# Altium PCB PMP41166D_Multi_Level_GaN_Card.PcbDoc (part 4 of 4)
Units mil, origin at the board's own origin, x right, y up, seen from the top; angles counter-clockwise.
Board outline 3221.72 x 1840 mil, 6 copper layers (Top Layer, Signal Layer 1, Signal Layer 2, Signal Layer 3, Signal Layer 4, Bottom Layer), stack 51.8 mil thick; 155 components, 123 nets, 580 pads, 278 vias.
Unrouted connection lines stored in the file: 2.
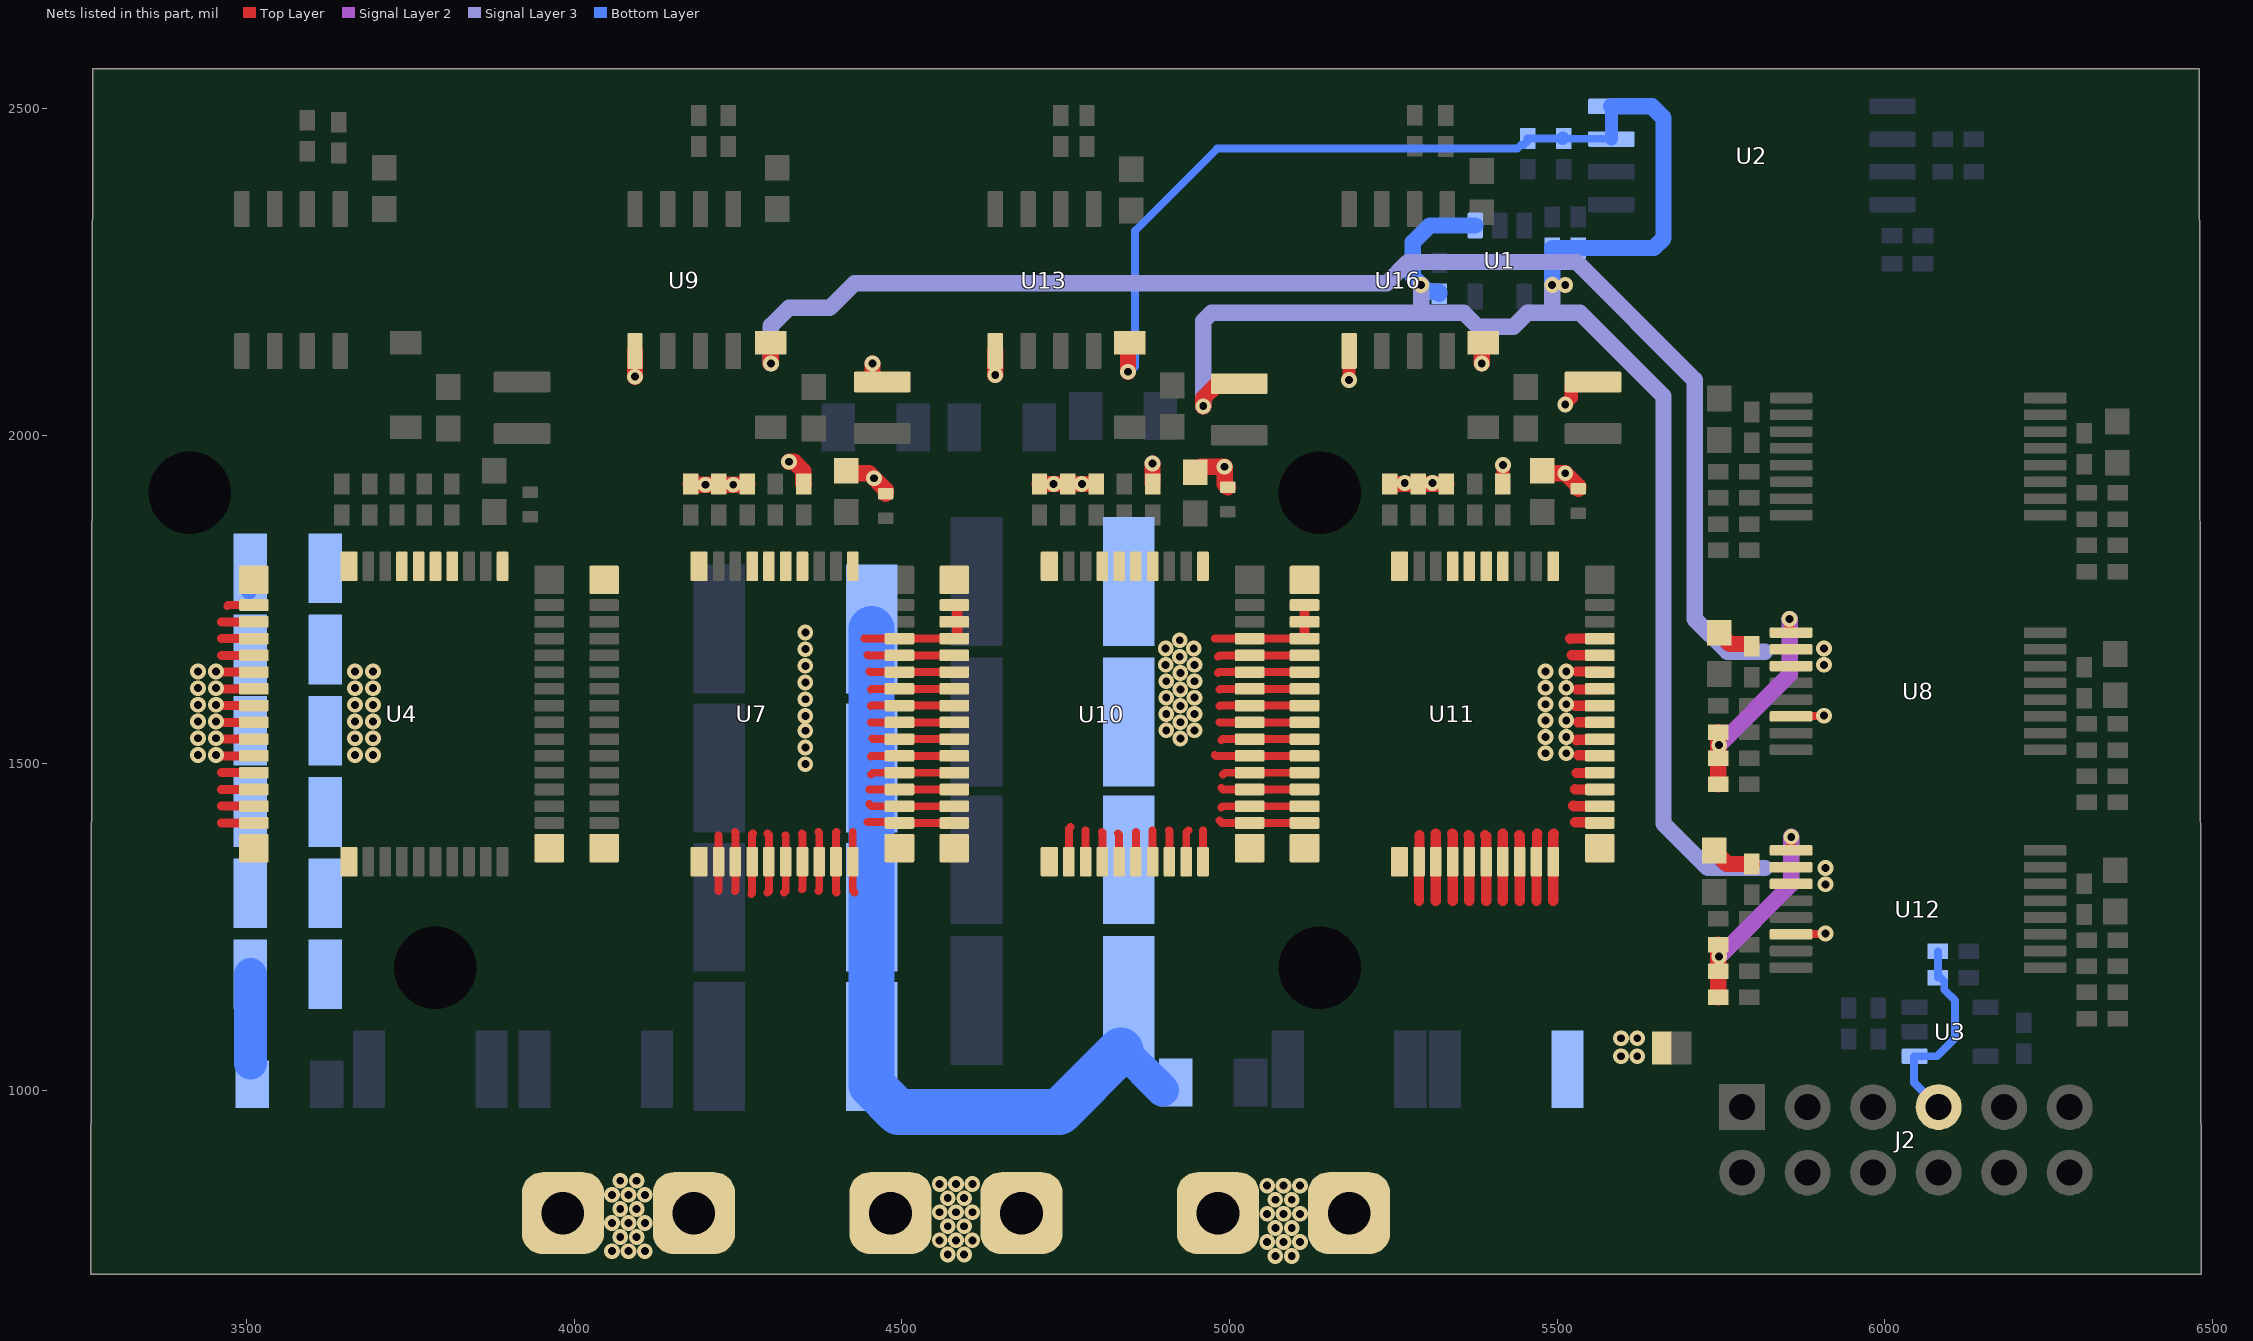
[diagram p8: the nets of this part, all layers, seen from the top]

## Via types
v1: diameter 24, hole 12, Top Layer to Bottom Layer, tented both sides, 278 vias

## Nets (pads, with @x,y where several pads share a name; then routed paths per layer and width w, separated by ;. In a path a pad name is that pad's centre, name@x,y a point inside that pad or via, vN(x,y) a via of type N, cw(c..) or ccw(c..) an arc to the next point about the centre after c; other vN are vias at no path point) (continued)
SGND_H3A: C30.2 C40.2 C41.2 C42.2 C43.1 C66.2 C67.2 C68.2 D9.2 L5.1 R10.1 R22.1 R24.1 SW.1 TP2.1 U7.18 U7.19 U7.20 U7.21 U7.22 U7.23 U7.24 U7.25 U7.26 U7.28 U7.29 U7.30 U7.31 U7.32 U7.33 U7.34 U7.35 U7.36 U7.37 U7.38 U7.39 U8.9 U8.10 U8.11 U8.14 U9.5 U10.2 U10.3 U10.4 U10.5 U10.6 U10.7 U10.8 U10.9 U10.10 U10.11 U10.12 U10.13 U10.14 U10.15 | length 5326
  Top Layer w12: 4220,1305 4220,1307.5 4220.17,1307.67 U7.18@4220.17,1349.61 4220.17,1389.83 4220,1390 ; 4245,1305 4245.76,1305.76 U7.19@4245.76,1349.61 4245.76,1394.24 4245,1395 ; 4270,1300 4271.35,1301.35 U7.20@4271.35,1349.61 4271.35,1391.35 4272.5,1392.5 ; 4295,1302.5 4296.94,1304.44 U7.21@4296.94,1349.61 4296.94,1390.56 4295,1392.5 ; 4320,1302.5 4322.53,1305.03 U7.22@4322.53,1349.61 4322.53,1389.97 ; 4347.5,1307.5 4348.12,1308.12 U7.23@4348.12,1349.61 4348.12,1391.88 4347.5,1392.5 ; 4372.5,1305 4373.71,1306.21 U7.24@4373.71,1349.61 4373.71,1393.79 4372.5,1395 ; 4400,1302.5 4399.3,1303.2 U7.25@4399.3,1349.61 4399.3,1394.3 4400,1395 ; 4425,1395 4424.9,1394.89 U7.26@4424.9,1349.61 4424.9,1305.11 4427.5,1302.5 ; 4442.5,1690 4442.66,1690.16 U7.39@4496.15,1690.16 U10.4@4579.99,1690.16 4584.31,1690.16 U10.4@4584.46,1690.31 ; 4447.5,1410 4494.82,1410 U7.28@4496.15,1408.66 U10.15@4579.99,1408.66 4584.31,1408.66 4584.46,1408.81 U10.15@4584.61,1408.66 ; 4447.5,1665 4447.93,1664.57 U7.38@4496.15,1664.57 U10.5@4579.99,1664.57 4584.31,1664.57 4584.46,1664.71 U10.5@4584.61,1664.57 ; 4450,1437.5 4453.25,1434.25 U7.29@4496.15,1434.25 U10.14@4579.99,1434.25 ; 4450,1460 4450.16,1459.84 U7.30@4496.15,1459.84 U10.13@4579.99,1459.84 4584.31,1459.84 4584.46,1459.99 U10.13@4584.61,1459.84 ; 4450,1640 4451.02,1638.98 U7.37@4496.15,1638.98 U10.6@4579.99,1638.98 4584.31,1638.98 4584.46,1639.12 U10.6@4584.61,1638.98 ; 4452.5,1482.5 4455.43,1485.43 U7.31@4496.15,1485.43 U10.12@4579.99,1485.43 4584.31,1485.43 4584.46,1485.58 U10.12@4584.61,1485.43 ; 4452.5,1510 4453.52,1511.02 U7.32@4496.15,1511.02 U10.11@4579.99,1511.02 4584.31,1511.02 4584.46,1511.17 U10.11@4584.61,1511.02 ; 4452.5,1562.5 4452.8,1562.2 U7.34@4496.15,1562.2 U10.9@4579.99,1562.2 4584.31,1562.2 4584.46,1562.35 U10.9@4584.61,1562.2 ; 4452.5,1587.5 4452.8,1587.8 U7.35@4496.15,1587.8 U10.8@4579.99,1587.8 4584.31,1587.8 4584.46,1587.94 U10.8@4584.61,1587.8 ; 4452.5,1612.5 4453.39,1613.39 U7.36@4496.15,1613.39 U10.7@4579.99,1613.39 4584.31,1613.39 4584.46,1613.53 U10.7@4584.61,1613.39 ; 4455,1537.5 4455.89,1536.61 U7.33@4496.15,1536.61 U10.10@4579.99,1536.61 4584.31,1536.61 4584.46,1536.76 U10.10@4584.61,1536.61 ; U10.14@4584.46,1434.4 U10.14@4584.61,1434.25 ; U8.9@5855,1701.34 5857.07,1699.27 U8.9@5857.2,1699.27 ; U8.14@5857.2,1571.32 5857.8,1571.91 5906.91,1571.91 v1(5907.5,1572.5)
  Top Layer w15: U8.9@5855,1701.34 v1(5855,1720)
  Top Layer w15.75: U10.4@4584.61,1690.31 U10.2@4584.61,1741.34
  Top Layer w25: v1(4092.5,2090) U9.5@4092.5,2129.23 ; C40.2@4177.5,1926.12 4177.5,1925.69 4178.19,1925 4219.94,1925 R10.1@4220.62,1925.69 ; R10.1@4220.62,1926.12 R10.1@4220.62,1925.69 ; C42.2@4263.75,1926.12 4263.75,1925.69 4263.06,1925 v1(4242.5,1925) 4221.31,1925 R10.1@4220.62,1925.69 ; v1(4300,2110) D9.2@4300,2141.97 ; v1(4327.5,1960) 4335.36,1960 4349.31,1946.04 4349.31,1926.81 C41.2@4350,1926.12 ; C30.2@4415,1946.5 4415,1945.51 4418.01,1942.5 4450,1942.5 4475,1917.5 C43.1@4475,1911.2 ; v1(4455,2110) 4455,2085.12 4458.25,2081.87 L5.1@4470,2081.87 ; R22.1@5746.38,1467.5 R24.1@5746.38,1547.5 ; C66.2@5747.5,1699 5747.5,1698.01 5763.64,1681.87 C67.2@5796.81,1681.87
  Signal Layer 2 w25: v1(5747.5,1527.5) 5855,1635 v1(5855,1720)
  Signal Layer 3 w25: v1(4300,2110) 4300,2167.5 4327.5,2195 4390,2195 4427.5,2232.5 5240,2232.5 5272.5,2265 5530,2265 5710,2085 5710,1720 5760,1670 5817.5,1670
  other v1: 4570,750 4595,750 4557.5,771.5 4582.5,771.5 4607.5,771.5 4570,793 4595,793 4557.5,814.5 4582.5,814.5 4607.5,814.5 4570,836 4595,836 4557.5,857.5 4582.5,857.5 4607.5,857.5 4352.5,1498.5 4352.5,1524 4352.5,1549.5 4352.5,1572 4352.5,1597.5 4352.5,1623 4352.5,1648.5 5907.5,1650 4352.5,1674 5907.5,1675 4352.5,1699.5 4200,1925 4457.5,1935
SGND_L2B: C5.1 C6.1 C7.1 C8.1 C9.1 C10.1 C58.2 C59.2 C60.2 C61.2 C62.1 D6.2 D11.2 L7.1 NT1.2 PGND.1 R14.1 TP3.1 U11.18 U11.19 U11.20 U11.21 U11.22 U11.23 U11.24 U11.25 U11.26 U11.28 U11.29 U11.30 U11.31 U11.32 U11.33 U11.34 U11.35 U11.36 U11.37 U11.38 U11.39 U16.5 | length 1689.4
  Top Layer w15.75: 5289.41,1289.9 U11.18@5289.41,1349.61 5290,1350.2 5290,1390 ; 5315,1289.9 U11.19@5315,1349.61 5315,1392.5 ; 5340,1392.5 5340.59,1391.91 U11.20@5340.59,1349.61 5340.59,1289.9 ; 5365,1390 5366.18,1388.82 U11.21@5366.18,1349.61 5366.18,1289.9 ; 5390,1390 5391.77,1388.23 U11.22@5391.77,1349.61 5391.77,1289.9 ; 5417.36,1289.9 U11.23@5417.36,1349.61 5417.36,1392.36 5417.5,1392.5 ; 5442.5,1390 5442.95,1389.55 U11.24@5442.95,1349.61 5442.95,1289.9 ; 5468.54,1289.9 U11.25@5468.54,1349.61 5469.53,1350.59 5469.53,1392.03 5470,1392.5 ; 5494.13,1289.9 U11.26@5494.13,1349.61 5494.13,1391.63 5495,1392.5 ; 5520,1690 5520.16,1690.16 U11.39@5565.39,1690.16 U11.39@5565.55,1690 ; 5522.5,1665 5522.93,1664.57 U11.38@5565.39,1664.57 U11.38@5565.83,1665 ; 5525,1435 5525.75,1434.25 U11.29@5565.39,1434.25 ; 5527.5,1410 5527.85,1409.65 5564.41,1409.65 U11.28@5565.39,1408.66 ; 5527.5,1460 5527.66,1459.84 U11.30@5565.39,1459.84 ; 5527.5,1587.5 5527.8,1587.8 U11.35@5565.39,1587.8 ; 5530,1485 5564.96,1485 U11.31@5565.39,1485.43 ; 5530,1535 5530.63,1535.63 5564.41,1535.63 U11.33@5565.39,1536.61 ; 5530,1612.5 5564.51,1612.5 U11.36@5565.39,1613.39 U11.36@5566.28,1612.5 ; 5530,1640 5530.04,1639.96 5564.41,1639.96 U11.37@5565.39,1638.98 U11.37@5566.38,1639.96 ; 5532.5,1512.5 5532.99,1512.01 5564.41,1512.01 U11.32@5565.39,1511.02 ; 5532.5,1562.5 5565.1,1562.5 U11.34@5565.39,1562.2
  Top Layer w20: v1@5181.73,2084.23 v1(5182.5,2085) U16.5@5182.5,2129.23 ; C60.2@5417.5,1940 v1(5417.5,1955) ; v1@5512.5,2046.42 v1(5512.5,2047.5) 5512.5,2048.58 5521.69,2057.78 5521.69,2076.12 L7.1@5527.44,2081.87
  Top Layer w25: C59.2@5245,1926.12 C61.2@5331.25,1926.12 ; v1(5385,2110) 5385,2139.47 D11.2@5387.5,2141.97 ; C58.2@5477.5,1941.5 5478.5,1942.5 v1(5512.5,1942.5) 5532.5,1922.5 C62.1@5532.5,1918.7 ; L7.1@5527.44,2081.87 L7.1@5555,2081.87
  other v1: 5070,747.5 5095,747.5 5057.5,769 5082.5,769 5107.5,769 5070,790.5 5095,790.5 5057.5,812 5082.5,812 5107.5,812 5070,833.5 5095,833.5 5057.5,855 5082.5,855 5107.5,855 5597.5,1052.5 5622.5,1052.5 5597.5,1080 5622.5,1080 3665,1512.5 3692.5,1512.5 5482.5,1515 5514,1515 3665,1538 3692.5,1538 5482.5,1540 5514,1540 3665,1563.5 3692.5,1563.5 5482.5,1565 5514,1565 3665,1589 3692.5,1589 5482.5,1590 5514,1590 3665,1614.5 3692.5,1614.5 5482.5,1615 5514,1615 3665,1640 3692.5,1640 5482.5,1640 5514,1640 5267.5,1927.5 5310,1927.5
SGND_L3B: C12.2 C13.2 C14.2 C15.2 C16.2 C17.2 C18.2 C19.2 C44.2 C45.2 C46.2 C47.2 C48.1 C49.2 C51.2 C54.2 C56.2 C73.2 C74.2 C75.2 D10.2 L6.1 R13.1 R31.1 R33.1 R53.1 R63.2 U1.1 U2.3 U2.4 U10.18 U10.19 U10.20 U10.21 U10.22 U10.23 U10.24 U10.25 U10.26 U10.28 U10.29 U10.30 U10.31 U10.32 U10.33 U10.34 U10.35 U10.36 U10.37 U10.38 U10.39 U11.2 U11.3 U11.4 U11.5 U11.6 U11.7 U11.8 U11.9 U11.10 U11.11 U11.12 U11.13 U11.14 U11.15 U12.9 U12.10 U12.11 U12.14 U13.5 | length 7642.9
  Top Layer w12: U10.18@4754.79,1349.61 4754.79,1399.79 4757.5,1402.5 ; 4780,1397.5 4780.38,1397.12 U10.19@4780.38,1349.61 ; 4805,1395 4805.97,1394.03 U10.20@4805.97,1349.61 ; 4830,1392.5 4831.56,1390.94 U10.21@4831.56,1349.61 ; U10.22@4857.15,1349.61 4857.15,1394.65 4857.5,1395 ; 4882.5,1397.5 4882.74,1397.26 U10.23@4882.74,1349.61 ; 4907.5,1397.5 4908.33,1396.67 U10.24@4908.33,1349.61 ; U10.25@4933.92,1349.61 4933.92,1393.92 4937.5,1397.5 ; U10.26@4959.51,1349.61 4959.51,1397.01 4960,1397.5 ; 4977.5,1512.5 4978.98,1511.02 U10.32@5030.77,1511.02 U11.11@5114.61,1511.02 ; 4977.5,1690 4977.66,1690.16 U10.39@5030.77,1690.16 U11.4@5114.61,1690.16 ; 4982.5,1637.5 4983.98,1638.98 U10.37@5030.77,1638.98 U11.6@5114.61,1638.98 ; 4982.5,1662.5 4984.57,1664.57 U10.38@5030.77,1664.57 U11.5@5114.61,1664.57 ; 4985,1412.5 4988.84,1408.66 U10.28@5030.77,1408.66 U11.15@5114.61,1408.66 ; 4985,1562.5 4985.3,1562.2 U10.34@5030.77,1562.2 U11.9@5114.61,1562.2 ; 4985,1587.5 4985.3,1587.8 U10.35@5030.77,1587.8 U11.8@5114.61,1587.8 ; 4985,1612.5 4985.89,1613.39 U10.36@5030.77,1613.39 U11.7@5114.61,1613.39 ; 4987.5,1432.5 4989.25,1434.25 U10.29@5030.77,1434.25 U11.14@5114.61,1434.25 ; 4987.5,1462.5 4990.16,1459.84 U10.30@5030.77,1459.84 U11.13@5114.61,1459.84 ; 4987.5,1535 4989.11,1536.61 U10.33@5030.77,1536.61 U11.10@5114.61,1536.61 ; 4990,1482.5 4992.93,1485.43 U10.31@5030.77,1485.43 U11.12@5114.61,1485.43 ; U12.14@5857.2,1238.82 5857.8,1239.41 5909.41,1239.41 v1(5910,1240) ; U12.9@5857.2,1366.77 U12.9@5857.5,1367.07
  Top Layer w15: U12.9@5857.5,1367.07 v1(5857.5,1387.5)
  Top Layer w15.75: U11.4@5114.61,1690.16 U11.2@5114.61,1741.34
  Top Layer w25: v1(4642.5,2092.5) U13.5@4642.5,2129.23 ; C45.2@4710,1926.12 R13.1@4753.12,1926.12 C47.2@4796.25,1926.12 ; v1(4845,2097.5) 4845,2129.47 D10.2@4847.5,2131.97 ; C46.2@4882.5,1926.12 v1(4882.5,1957.5) ; C44.2@4947.5,1944 4947.5,1944.98 4953.7,1951.18 4954.69,1951.18 4956,1952.5 v1(4992.5,1952.5) 4992.5,1926.2 C48.1@4997.5,1921.2 ; v1(4960,2045) 4960,2056.93 4982.44,2079.37 5010,2079.37 L6.1@5007.5,2081.87 ; C73.2@5740,1366.5 5740,1365.51 5759.39,1346.12 C74.2@5797.5,1346.12 ; R31.1@5746.38,1142.5 R33.1@5746.38,1222.5
  Signal Layer 2 w25: v1(5747.5,1205) 5857.5,1315 v1(5857.5,1387.5)
  Signal Layer 3 w25: v1(4960,2045) 4960,2175 4972.5,2187.5 5357.5,2187.5 5379,2166 5433.5,2166 5455,2187.5 5535,2187.5 5662.5,2060 5662.5,1407.5 5730,1340 5817.5,1340 ; 5292.5,2200.96 v1(5292.5,2230) ; 5492.5,2202.27 v1(5492.5,2230)
  Bottom Layer w12: v1(4845,2097.5) 4848.25,2097.5 4856,2105.25 4856,2312.87 4981.13,2438 5439.38,2438 5445.25,2443.87 5449.19,2443.87 5455,2449.68 R53.1@5455,2453.62 C56.2@5508.62,2453.62 ; C56.2@5509.31,2454.31 C56.2@5510,2453.62 5510.56,2453.06 5582.37,2453.06 U2.3@5582.93,2452.5
  Bottom Layer w20: C56.2@5508.62,2453.62 C56.2@5509.31,2454.31 ; U2.3@5582.93,2452.5 U2.4@5582.93,2502.5
  Bottom Layer w25: C49.2@5320,2216.38 5320,2218.94 5319.31,2219.63 5302.87,2219.63 v1(5292.5,2230) 5280,2242.5 5280,2295 5305.77,2320.77 U1.1@5375.2,2320.77 ; v1@5492.5,2232.5 5493.19,2285.69 C54.2@5492.5,2286.38 C51.2@5532.5,2286.38 5647.86,2286.38 5662.5,2301.02 5662.5,2485 5645,2502.5 U2.4@5582.93,2502.5
  Bottom Layer w50: C16.2@4833.92,1061.42 4837.32,1061.42 R63.2@4897.91,1000.83
  Bottom Layer w70: C15.2@4453.64,1705 C14.2@4453.64,1492.5 C13.2@4453.64,1280 C12.2@4453.64,1067.5 4453.64,1008.44 4494.59,967.5 4740,967.5 C16.2@4833.92,1061.42
  other v1: 5910,1315 5910,1340 4925,1537.5 4903.5,1550 4946.5,1550 4925,1562.5 4903.5,1575 4946.5,1575 4925,1587.5 4903.5,1600 4946.5,1600 4925,1612.5 4903.5,1625 4946.5,1625 4925,1637.5 4902.5,1650 4946.5,1650 4924,1662.5 4902.5,1675 4945.5,1675 4924,1687.5 4731.56,1926.12 4774.69,1926.12 5512.5,2230
TH1: TH1.1
TH2: TH2.1
TH3: TH3.1
TH4: TH4.1
U4_1: U4.1
U4_16: U4.16
U4_17: U4.17
U4_27: U4.27
U4_43: U4.43
U4_47: U4.47
U4_52: U4.52
U4_FAULT: U4.46
U4_OC: U4.48
U4_TEMP: U4.49
U7_1: U7.1
U7_16: U7.16
U7_17: U7.17
U7_27: U7.27
U7_43: U7.43
U7_47: U7.47
U7_52: U7.52
U7_FAULT: U7.46
U7_OC: U7.48
U7_TEMP: U7.49
U10_1: U10.1
U10_16: U10.16
U10_17: U10.17
U10_27: U10.27
U10_43: U10.43
U10_47: U10.47
U10_52: U10.52
U10_FAULT: U10.46
U10_OC: U10.48
U10_TEMP: U10.49
U11_1: U11.1
U11_16: U11.16
U11_17: U11.17
U11_27: U11.27
U11_43: U11.43
U11_47: U11.47
U11_52: U11.52
U11_FAULT: U11.46
U11_OC: U11.48
U11_TEMP: U11.49
Vbulk1: BULK.1 C5.2 C6.2 C7.2 C8.2 C9.2 C10.2 R30.2 TP1.1 U4.2 U4.3 U4.4 U4.5 U4.6 U4.7 U4.8 U4.9 U4.10 U4.11 U4.12 U4.13 U4.14 U4.15 | length 821.4
  Top Layer w12: 3470,1740 3471.34,1741.34 U4.2@3510.75,1741.34
  Top Layer w13.78: 3461.34,1408.66 U4.15@3510.75,1408.66 ; 3461.34,1434.25 U4.14@3510.75,1434.25 ; 3461.34,1459.84 U4.13@3510.75,1459.84 ; 3461.34,1485.43 U4.12@3510.75,1485.43 ; v1@3461.34,1511.02 U4.11@3510.75,1511.02 ; v1@3461.34,1536.61 U4.10@3510.75,1536.61 ; v1@3461.34,1562.2 U4.9@3510.75,1562.2 ; v1@3461.34,1587.8 U4.8@3510.75,1587.8 ; v1@3461.34,1613.39 U4.7@3510.75,1613.39 ; v1@3461.34,1638.98 U4.6@3510.75,1638.98 ; 3461.34,1664.57 U4.5@3510.75,1664.57 ; 3461.34,1690.16 U4.4@3510.75,1690.16 ; 3461.34,1715.75 U4.3@3510.75,1715.75
  Bottom Layer w25: C5.2@3501.87,1763.96 C5.2@3503.33,1762.5
  Bottom Layer w50: R30.2@3505.41,1041.79 C10.2@3505.41,1177.5
  other v1: 4057.5,755 4082.5,755 4107.5,755 4070,776.5 4095,776.5 4057.5,798 4082.5,798 4107.5,798 4070,819.5 4095,819.5 4057.5,841 4082.5,841 4107.5,841 4070,862.5 4095,862.5 3425.5,1512.5 3453,1512.5 3425.5,1538 3453,1538 3425.5,1563.5 3453,1563.5 3425.5,1589 3453,1589 3425.5,1614.5 3453,1614.5 3425.5,1640 3453,1640
VFLY_SENSE: C50.2 J2.7 R1.1 U3.1 | length 313.9
  Bottom Layer w12: R1.1@6081.38,1212.5 C50.2@6081.38,1172.5 6085.31,1172.5 6091.13,1166.69 6091.13,1154.23 6107.5,1137.86 6107.5,1080 6080.1,1052.6 U3.1@6045.87,1052.6 6045,1051.73 6045,1012.5 J2.7@6082.5,975 J2.7@6083.75,976.25
pads on no net: U5.13 U8.13 U12.13

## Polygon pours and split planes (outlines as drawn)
PGND on Bottom Layer "BOTTOM_LAYER_PGND_P417" (solid, pour order 417): 5974.67,2545.92 6434.67,2545.92 6467.17,2513.42 6467.17,778.42 6427.17,738.42 5719.67,738.42 5684.67,773.42 5684.67,1088.42 5724.67,1128.42 5889.67,1128.42 5974.67,1213.42 5974.67,2108.42
SGND_L3B on Bottom Layer "BOTTOM_LAYER_SGND_L3B_P372" (solid, pour order 372): 4830,1870 4885,1870 4900,1855 4900,1745 4960,1685 4960,1517.5 4900,1457.5 4900,1045 4895,1040 4815,1040 4815,1855
SGND_L2B on Bottom Layer "BOTTOM_LAYER_SGND_L2B_P401" (solid, remove dead copper, pour order 401): 5605.78,719.04 4916.45,727.5 4916.45,882.5 5395.42,882.5 5445,951.15 5445,1657.83 5498.17,1692.5 5617.5,1692.5 5647.5,1662.5 5647.5,754.5
Vbulk1 on Bottom Layer "BOTTOM_LAYER_VBULK1_P400" (solid, remove dead copper, pour order 400): 3912.5,735 3912.5,887.1 4257.5,887.1 4257.5,735
SGND_L3B on Bottom Layer "BOTTOM_LAYER_SGND_L3B_P399" (solid, pour order 399): 5520,2277.5 5525,2272.5 5525,2222.5 5520,2217.5 5487.5,2217.5 5482.5,2222.5 5482.5,2275 5485,2277.5
SGND_L2B on Bottom Layer "BOTTOM_LAYER_SGND_L2B_P380" (solid, pour order 380): 3602.5,1835 3652.5,1835 3680,1807.5 3680,1687.5 3712.5,1655 3712.5,1500 3690,1477.5 3690,1180 3640,1130 3602.5,1130
Vbulk1 on Bottom Layer "BOTTOM_LAYER_VBULK1_P379" (solid, pour order 379): 3470,1835 3432.5,1797.5 3432.5,1682.5 3407.5,1657.5 3407.5,1502.5 3425,1485 3432.5,1477.5 3432.5,1170 3475,1127.5 3525,1127.5 3525,1835
SGND_H2A on Bottom Layer "BOTTOM_LAYER_SGND_H2A_P371" (solid, pour order 371): 4182.5,1807.5 4165,1790 4165,1752.5 4092.5,1680 4092.5,1542.5 4165,1470 4165,980 4170,975 4252.5,975 4252.5,1807.5
no net on Bottom Layer "BOTTOM_LAYER_NONET_P370" (solid, pour order 370): 4247.5,1847.5 4230,1847.5 4225,1842.5
SGND_H3A on Bottom Layer "BOTTOM_LAYER_SGND_H3A_P349" (solid, remove dead copper, pour order 349): 6330,1540 6440,1540 6440,1605 6330,1605
SGND_H3A on Bottom Layer "BOTTOM_LAYER_SGND_H3A_P159" (solid, remove dead copper, pour order 159): 4412.5,729.71 4412.5,881.81 4757.5,881.81 4757.5,729.71
SGND_L3B on Top Layer "TOP_LAYER_SGND_L3B_P420" (solid, pour order 420): 5802.25,1361.7 5814.75,1361.7 5824.75,1351.7 5919.75,1351.7 5924.75,1346.7 5924.75,1310.98 5920.47,1306.7 5829.75,1306.7 5797.94,1338.51 5797.94,1357.38 5799.75,1359.2
SGND_H3A on Top Layer "TOP_LAYER_SGND_H3A_P419" (solid, pour order 419): 5800,1695 5812.5,1695 5822.5,1685 5917.5,1685 5922.5,1680 5922.5,1644.28 5918.22,1640 5827.5,1640 5795.69,1671.81 5795.69,1690.69 5797.5,1692.5
SGND_H2A on Top Layer "TOP_LAYER_SGND_H2A_P418" (solid, pour order 418): 5800,2052.5 5812.5,2052.5 5822.5,2042.5 5917.5,2042.5 5922.5,2037.5 5922.5,2001.78 5918.22,1997.5 5827.5,1997.5 5795.69,2029.31 5795.69,2048.19 5797.5,2050
SGND_H2A on Top Layer "TOP_LAYER_SGND_H2A_P397" (solid, pour order 397): 4075,1750 4097.5,1750 4105,1742.5 4105,1712.5 4117.5,1700 4147.5,1700 4167.5,1680 4167.5,1540 4147.5,1520 4125,1520 4105,1500 4105,1415 4090,1400 4072.57,1400 4072.57,1747.57
PGND on Top Layer "TOP_LAYER_PGND_P414" (solid, pour order 414): 6232.5,1127.5 6337.5,1022.5 6337.5,777.5 6295,735 5725,735 5685,775 5685,1090 5722.5,1127.5
PGND on Top Layer "TOP_LAYER_PGND_P412" (solid, pour order 412): 6237.5,1415 6392.5,1415 6400,1407.5 6400,1320 6377.5,1297.5 6292.5,1297.5 6280,1285 6242.5,1285 6230,1297.5 6230,1407.5
PGND on Top Layer "TOP_LAYER_PGND_P409" (solid, pour order 409): 6245,1770 6385,1770 6400,1755 6400,1652.5 6377.5,1630 6292.5,1630 6280,1617.5 6242.5,1617.5 6230,1630 6230,1755
PGND on Top Layer "TOP_LAYER_PGND_P406" (solid, pour order 406): 6242.5,2147.5 6377.5,2147.5 6400,2125 6400,1997.5 6390,1987.5 6292.5,1987.5 6280,1975 6242.5,1975 6230,1987.5 6230,2135
SGND_L2B on Top Layer "TOP_LAYER_SGND_L2B_P288" (solid, remove dead copper, pour order 288): 5280,1377.5 5280,1413.32 5297.25,1445 5425.08,1445 5452.5,1479.55 5452.5,1683.59 5477.67,1700 5537.5,1700 5537.5,1400 5515,1377.5
Vbulk1 on Top Layer "TOP_LAYER_VBULK1_P396" (solid, pour order 396): 3463.5,1749.51 3369.51,1749.51 3310,1690 3310,945 3510,745 4230,745 4257.5,772.5 4257.5,892.5 4197.5,952.5 3682.5,952.5 3478.5,1156.5 3478.5,1749.51 3440.49,1749.51 3440,1750
SGND_L3B on Top Layer "TOP_LAYER_SGND_L3B_P384" (solid, pour order 384): 5000,1702.5 4895,1702.5 4882.5,1690 4882.5,1510 4822.5,1450 4765,1450 4747.5,1432.5 4747.5,1385 4975,1385 5000,1410
SGND_H3A on Top Layer "TOP_LAYER_SGND_H3A_P383" (solid, pour order 383): 4464.47,1727.5 4357.5,1727.5 4340,1710 4340,1457.5 4323.51,1441.01 4236.97,1441.01 4214.47,1418.51 4214.47,1381.01 4449.47,1381.01 4464.47,1396.01
SGND_H3A on Top Layer "TOP_LAYER_SGND_H3A_P375" (solid, pour order 375): 4210,1320 4210,1127.5 4405,932.5 4405,775 4445,735 4727.5,735 4760,767.5 4760,887.5 4447.5,1200 4447.5,1320
SGND_H2A on Top Layer "TOP_LAYER_SGND_H2A_P374" (solid, pour order 374): 3926.25,1701.25 3883.75,1701.25 3856.25,1673.75 3856.25,1486.25 3813.75,1443.75 3698.75,1443.75 3676.25,1421.25 3676.25,1383.75 3911.25,1383.75 3926.25,1398.75
SGND_L2B on Top Layer "TOP_LAYER_SGND_L2B_P299" (solid, remove dead copper, pour order 299): 5662.5,725 5662.5,1295.34 5646.69,1305.16 5282.5,1305.16 5282.5,916.62 5248.23,887.5 4912.5,887.5 4912.5,725
SGND_L2B on Signal Layer 1 "SIGNAL_LAYER_1_SGND_L2B_P392" (solid, pour order 392): 5170,2155 5360,2155 5420,2095 5572.5,2095 5637.5,2030 5637.5,1562.5 5567.5,1492.5 5475,1492.5 5457.5,1510 5457.5,1817.5 5435,1840 5262.5,1840 5150,1952.5 5150,2135
PGND on Signal Layer 1 "SIGNAL_LAYER_1_PGND_P416" (solid, pour order 416): 3350,2512.5 3382.5,2545 6435,2545 6467.5,2512.5 6467.5,777.5 6427.5,737.5 5720,737.5 5685,772.5 5685,1087.5 5725,1127.5 5890,1127.5 5975,1212.5 5975,2107.5 5787.5,2295 3392.5,2295 3350,2337.5
no net on Signal Layer 1 "SIGNAL_LAYER_1_NONET_P415" (solid, pour order 415): 2327.5,-1516.5 2360,-1484 5412.5,-1484 5445,-1516.5 5445,-3251.5 5405,-3291.5 4697.5,-3291.5 4662.5,-3256.5 4662.5,-2941.5 4702.5,-2901.5 4867.5,-2901.5 4952.5,-2816.5 4952.5,-1921.5 4765,-1734 2370,-1734 2327.5,-1691.5
SGND_L3B on Signal Layer 1 "SIGNAL_LAYER_1_SGND_L3B_P391" (solid, pour order 391): 4625,2095 4642.5,2112.5 4915,2112.5 5007.5,2020 5007.5,1937.5 4970,1900 4970,1545 4942.5,1517.5 4897.5,1517.5 4870,1545 4870,1830 4790,1910 4675,1910 4625,1960
SGND_H3A on Signal Layer 1 "SIGNAL_LAYER_1_SGND_H3A_P386" (solid, pour order 386): 4447.5,1707.5 4347.5,1707.5 4337.5,1697.5 4337.5,1462.5 4315.8,1440.8 4236.68,1440.8 4210,1414.12 4210,1380.8 4447.5,1380.8
SGND_H2A on Signal Layer 1 "SIGNAL_LAYER_1_SGND_H2A_P388" (solid, pour order 388): 3800,2112.5 3930,1982.5 3930,1702.5 3930,1530 3917.5,1517.5 3860,1517.5 3835,1542.5 3835,1710 3745,1800 3607.5,1937.5 3577.5,1937.5 3477.5,2037.5 3477.5,2095 3495,2112.5
SGND_L2B on Signal Layer 1 "SIGNAL_LAYER_1_SGND_L2B_P300" (solid, remove dead copper, pour order 300): 5585.19,719.29 4916.45,727.5 4916.45,882.5 5395.42,882.5 5457.5,968.46 5457.5,1665.98 5498.17,1692.5 5587.5,1692.5 5637.5,1642.5 5637.5,763.75
Vbulk1 on Signal Layer 1 "SIGNAL_LAYER_1_VBULK1_P382" (solid, pour order 382): 3463.5,1749.51 3369.51,1749.51 3310,1690 3310,945 3510,745 4230,745 4257.5,772.5 4257.5,892.5 4197.5,952.5 3682.5,952.5 3478.5,1156.5 3478.5,1749.51 3440.49,1749.51 3440,1750
SGND_H3A on Signal Layer 1 "SIGNAL_LAYER_1_SGND_H3A_P389" (solid, pour order 389): 4087.5,2135 4307.5,2135 4317.5,2125 4462.5,2125 4472.5,2115 4472.5,1705 4437.5,1670 4337.5,1670 4337.5,1867.5 4295,1910 4130,1910 4057.5,1982.5 4057.5,2105
SGND_H3A on Signal Layer 1 "SIGNAL_LAYER_1_SGND_H3A_P387" (solid, pour order 387): 4209.46,1392.5 4209.46,1127.97 4404.46,932.97 4404.46,775.47 4444.46,735.47 4726.96,735.47 4759.46,767.97 4759.46,887.97 4446.96,1200.47 4446.96,1392.5
SGND_L3B on Signal Layer 3 "SIGNAL_LAYER_3_SGND_L3B_P411" (solid, pour order 411): 5805,1360 5912.5,1360 5925,1347.5 5925,1207.5 5900,1182.5 5745,1182.5 5735,1192.5 5735,1217.5 5800,1282.5 5800,1355
SGND_H3A on Signal Layer 3 "SIGNAL_LAYER_3_SGND_H3A_P408" (solid, pour order 408): 5802.5,1692.5 5910,1692.5 5922.5,1680 5922.5,1540 5897.5,1515 5742.5,1515 5732.5,1525 5732.5,1550 5797.5,1615 5797.5,1687.5
SGND_H2A on Signal Layer 3 "SIGNAL_LAYER_3_SGND_H2A_P405" (solid, pour order 405): 5802.5,2050 5910,2050 5922.5,2037.5 5922.5,1897.5 5897.5,1872.5 5742.5,1872.5 5732.5,1882.5 5732.5,1907.5 5797.5,1972.5 5797.5,2045
SGND_L3B on Signal Layer 3 "SIGNAL_LAYER_3_SGND_L3B_P398" (solid, pour order 398): 5517.5,2242.5 5525,2235 5525,2197.5 5522.5,2195 5485,2195 5480,2200 5480,2235 5487.5,2242.5 5480,2235 5487.5,2242.5
PGND on Signal Layer 4 "SIGNAL_LAYER_4_PGND_P413" (solid, pour order 413): 3350,2512.5 3382.5,2545 6435,2545 6467.5,2512.5 6467.5,777.5 6427.5,737.5 5720,737.5 5685,772.5 5685,1087.5 5725,1127.5 5890,1127.5 5975,1212.5 5975,2107.5 5787.5,2295 3392.5,2295 3350,2337.5
SGND_L2B on Signal Layer 2 "SIGNAL_LAYER_2_SGND_L2B_P381" (solid, pour order 381): 3705,1657.5 3715,1647.5 3715,1510 3775,1450 5422.5,1450 5460,1487.5 5460,1645 5477.5,1662.5 5527.5,1662.5 5537.5,1652.5 5537.5,1390 5497.5,1350 5495,1352.5 3700,1352.5 3642.5,1410 3642.5,1647.5 3652.5,1657.5

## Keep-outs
Keep-Out Layer:
  text ".Layer_Name" at 3789.5,536.51 h60

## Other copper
Top Layer:
  text ".Layer_Name" at 172.5,-27.5 h60
Bottom Layer:
  text ".Layer_Name" at 147,-33.49 h60

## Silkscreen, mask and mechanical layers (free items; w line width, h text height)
Top Overlay:
  text "VBULK1" at 3932.5,903.54 h86.61
  text "SW" at 4507.5,903.54 h86.61
  text "PGND" at 4977.5,903.54 h86.61
  text ".Layer_Name" at 147,-33.49 h60
Bottom Overlay:
  text "PMP41166D" at 5067.5,2371.04 h86.61
  text "Multi Level PSU GaN Card" at 5075,2276.04 h86.61
  text ".Layer_Name" at 147,-33.49 h60
Top Paste:
  text ".Layer_Name" at 577,-858.49 h60
Bottom Paste:
  text ".Layer_Name" at 577,-858.49 h60
Top Solder:
  text ".Layer_Name" at 577,-858.49 h60
  text ".Layer_Name" at 577,-858.49 h60
Bottom Solder:
  text ".Layer_Name" at 3789.5,536.51 h60
Drill Guide:
  text ".Layer_Name" at 3789.5,536.51 h60
M1 Board Outline:
  lines w7.01: 3262.5,2567.5 3261.7,720 6483.42,720 6482.5,2567.5 ; 3263.86,2567.5 6480,2567.5
  text ".Layer_Name" at 147,-33.49 h60
M2 Board Dimensions:
  rectangle: 125,-400 500,-275
  rectangle: 0,-275 125,-150
  lines w7: 0,-275 1000,-275 ; 125,-400 125,-150 ; 250,-400 250,-150 ; 500,-400 500,-150 ; 750,-400 750,-150 ; 0,-400 0,-150 1000,-150 1000,-400 0,-400
  text ".Layer_Name" at 577,-858.49 h60
M3 3D STEP Top:
  lines w10: 4567.73,1765.28 6525.64,1765.28
  text ".Layer_Name" at 577,-858.49 h60
M4 3D STEP Bottom:
  text ".Layer_Name" at 577,-858.49 h60
M5 Assembly Top:
  lines w10: -292,-930.17 6308,-930.17 ; -292,-726.83 6310,-726.83 ; -292,-523.5 -292,-1133.5 3713,-1133.5 6310,-1133.5 6310,-523.5 -291.5,-523.5 -291.5,-1133.5 1284,-1133.5 ; 2173,-1133.5 2173,-523.5 ; 3440,-726.83 3440,-523.5 ; 4280,-726.83 4280,-523.5 ; 4902,-1140 4902,-937.17
  text "COMPONENTS MARKED 'DNP' SHOULD NOT BE POPULATED." at 1153.5,-318.5 h60
  text "ASSEMBLY VARIANT:" at 1153,-434 h60
  text ".VariantName" at 2189,-434 h60
  text "PCB VIEWED FROM TOP SIDE" at -228.5,-655.67 h60
  text "BOARD #:" at 2248,-655.67 h60
  text ".PRJ_Number" at 2793.5,-655.67 h60
  text "REV:" at 3638,-655.67 h60
  text ".PCB_Rev" at 3929.5,-655.67 h60
  text "SVN REV:" at 4476,-655.67 h60
  text ".VersionControl_RevNumber" at 4982,-655.67 h60
  text "TID #:" at 2248,-859 h60
  text ".TID" at 2793.5,-859 h60
  text "PLOT NAME =" at -228.5,-1064.34 h60
  text ".plot_File_Name" at 577,-1064.34 h60
  text "GENERATED    :" at 2250,-1064.34 h60
  text ".Print_Date" at 3119.5,-1064.34 h60
  text ".Print_Time" at 3848.5,-1064.34 h60
  text "TEXAS INSTRUMENTS" at 5113,-1064.34 h60
M6 Assembly Bottom:
  lines w10: -292.5,-727.33 6309.5,-727.33 ; -290.5,-930.67 6309.5,-930.67 ; 1115.5,-1140.5 1115.5,-937.67 ; 1737.5,-727.33 1737.5,-524 ; 2577.5,-727.33 2577.5,-524 ; 3844.5,-1134 3844.5,-524 ; 4733.5,-1134 6309,-1134 6309,-524 -292.5,-524 -292.5,-1134 2304.5,-1134 6309.5,-1134 6309.5,-524
  text "COMPONENTS MARKED 'DNP' SHOULD NOT BE POPULATED." at 6853.97,-314.06 h60
  text ".VariantName" at 5058,-434 h60
  text "ASSEMBLY VARIANT:" at 6097,-434 h60
  text ".VersionControl_RevNumber" at 1035.5,-656.17 h60
  text "SVN REV:" at 1541.5,-656.17 h60
  text ".PCB_Rev" at 2088,-656.17 h60
  text "REV:" at 2379.5,-656.17 h60
  text ".PRJ_Number" at 3224,-656.17 h60
  text "BOARD #:" at 3769.5,-656.17 h60
  text "PCB VIEWED FROM BOTTOM SIDE" at 6246,-656.17 h60
  text ".TID" at 3224,-859.5 h60
  text "TID #:" at 3769.5,-859.5 h60
  text "TEXAS INSTRUMENTS" at 904.5,-1064.84 h60
  text ".Print_Time" at 2169,-1064.84 h60
  text ".Print_Date" at 2898,-1064.84 h60
  text "GENERATED    :" at 3767.5,-1064.84 h60
  text ".plot_File_Name" at 5440.5,-1064.84 h60
  text "PLOT NAME =" at 6246,-1064.84 h60
M9 Title Sheet:
  drawing of 57 lines, arcs and shapes, not listed
  text "1" at 739.84,8036.5 h70
  text "2" at 3235.5,8036.5 h70
  text "3" at 5724.84,8036.5 h70
  text "4" at 8231.51,8036.5 h70
  text "5" at 10730.5,8036.5 h70
  text "6" at 13235.5,8036.5 h70
  text "A" at -416.5,6893.5 h70
  text "A" at 14383.5,6893.5 h70
  text "B" at -416.5,4513.5 h70
  text "B" at 14383.5,4513.5 h70
  text "C" at -416.5,2138.5 h70
  text "C" at 14383.5,2138.5 h70
  text "PROJECT TITLE:" at 11343.5,277.5 h45
  text ".PRJ_Title" at 11393.5,144.17 h70
  text "DESIGNED FOR:" at 11343.5,-23.5 h45
  text ".PRJ_Customer" at 11393.5,-163.5 h70
  text "D" at -416.5,-231.5 h70
  text "D" at 14383.5,-231.5 h70
  text "FILE NAME:" at 11343.5,-323.5 h45
  text ".PCB_File_Name_No_Path" at 11393.5,-443.5 h70
  text "Texas Instruments (TI) and/or its licensors do not warrant the accuracy or completeness of this specification" at 6374,-605.34 h45
  text "ENGINEER:" at 11343.5,-613.5 h45
  text "LAYOUT BY:" at 12848.5,-613.5 h45
  text "or any information contained therein. TI and/or its licensors do not warrant that this design will meet" at 6329.01,-718 h45
  text ".PRJ_Engineer" at 11393.5,-768.49 h70
  text ".PCB_Layout" at 12899,-768.49 h70
  text "the specifications, will be suitable for your application or fit for any particular purpose, or will operate in" at 6329.01,-830.67 h45
  text ".Layer_Name" at 577,-858.49 h60
  text "ALTIUM DESIGNER VERSION:" at 12848.5,-923.5 h45
  text "an implementation. TI and/or its licensors do not warrant that the design is production worthy. You should" at 6329.01,-943.33 h45
  text "completely validate and test your design implementation to confirm the system functionality for your application." at 6374,-1056 h45
  text ".print_Scale" at 11393.5,-1056.83 h70
  text ".Application_BuildNumber" at 12899,-1056.83 h70
  text "1" at 739.84,-1263.5 h70
  text "2" at 3235.5,-1263.5 h70
  text "3" at 5724.84,-1263.5 h70
  text "4" at 8231.51,-1263.5 h70
  text "5" at 10730.5,-1263.5 h70
  text "6" at 13235.5,-1263.5 h70
M10 Fab Notes:
  drawing of 189 lines, arcs and shapes, not listed
  text "DESIGN INFORMATION" at 12382.02,6356.17 h60
  text "MIN. TRACK WIDTH:" at 11737.46,6224.05 h60
  text "8" at 12833.7,6224.05 h60
  text "MIL" at 12988.46,6224.05 h60
  text "MIN. CLEARANCE:" at 11737.46,6099.92 h60
  text "0.2" at 12773.7,6099.93 h60
  text "mm" at 12988.46,6099.92 h60
  text "MIN. VIA PAD SIZE:" at 11737.46,5975.8 h60
  text "20" at 12803.71,5975.8 h60
  text "MIL" at 12988.46,5975.8 h60
  text "0.05mm (2MIL)" at 12432.46,5845.9 h60
  text "MINIMUM ANNULAR RING" at 11408.23,5837.67 h60
  text "EXTERNAL" at 13140.46,5837.67 h60
  text "PER" at 11608.23,5727.55 h60
  text "IPC-D-275 CLASS 2 LEVEL C" at 11828.23,5727.54 h60
  text "MIL, HOLES" at 13316.46,5627.07 h60
  text "+/-" at 12924,5618.48 h60
  text "+/-" at 13778,5618.48 h60
  text "REGISTRATION TOLERANCES:" at 11408.23,5617.42 h60
  text "METAL" at 12608,5617.42 h60
  text "5" at 13184.2,5617.42 h60
  text "3" at 14017.2,5617.42 h60
  text "MIL" at 14133.46,5617.42 h60
  text "HOLE SIZE TOLERANCE (UNLESS OTHERWISE SPECIFIED):" at 11408.23,5519.1 h60
  text "+/-" at 13778,5516.23 h60
  text "3" at 14017.2,5515.17 h60
  text "MIL" at 14133.46,5515.17 h60
  text "MATERIAL:" at 11333.46,5377.52 h60
  text "FR-4 High Tg" at 12319.9,5249 h60
  text "X" at 12175.46,5241.01 h60
  text "FR-408" at 11754.46,5236.49 h60
  text "OTHER" at 13242.46,5236.49 h60
  text "62 MIL (1.6mm) +/-10%" at 12074.56,5093.46 h60
  text "X" at 11954.46,5091.01 h60
  text "THICKNESS:" at 11408.23,5085.24 h60
  text "OTHER" at 13359.46,5085.24 h60
  text "TOLERANCE:" at 11408.23,4946.92 h60
  text "X" at 12256.46,4946.92 h60
  text "ANSI IPC-6012 TYPE 3 CLASS 2" at 12434.48,4946.92 h60
  text "OTHER +/-" at 12434.46,4802.73 h60
  text "BOW & TWIST:" at 11408.23,4657.54 h60
  text "X" at 12256.46,4657.54 h60
  text "ANSI IPC-6012 TYPE 3 CLASS 2" at 12434.48,4657.54 h60
  text "OTHER +/-" at 12434.46,4510.85 h60
  text "DRILLING:" at 11333.46,4380.23 h60
  text "NC_DRILL FILES" at 13094.46,4275.04 h60
  text "REFERENCE:" at 11408.23,4271.1 h60
  text "X" at 12065.46,4271.01 h60
  text "AS SHOWN" at 12243.46,4271.1 h60
  text "X" at 12966.46,4271.1 h60
  text "OTHER" at 13392.46,4128.85 h60
  text "PTH COPPER THICKNESS:" at 11407.91,4125.32 h60
  text "X" at 12547.14,4125.32 h60
  text "20-30 um" at 12675.14,4125.32 h60
  text "BOARD FINISH:" at 11333.46,3977.73 h60
  text "SILKSCREEN:" at 11488.68,3867.6 h60
  text "X" at 12446.46,3867.6 h60
  text "TOP" at 12563.46,3867.6 h60
  text "X" at 12956.46,3867.6 h60
  text "BOTTOM" at 13074.46,3867.6 h60
  text "SILKSCREEN COLOR:" at 11488.68,3712.41 h60
  text "X" at 12445.46,3712.41 h60
  text "WHITE" at 12563.46,3712.41 h60
  text "OTHER" at 13074.46,3712.41 h60
  text "X" at 12576.46,3568.96 h60
  text "GREEN" at 12694.46,3568.96 h60
  text "OTHER" at 13312.46,3568.96 h60
  text "SOLDER RESIST COLOR:" at 11488.68,3562.1 h60
  text "X" at 12576.46,3414.71 h60
  text "MATTE" at 12694.46,3414.71 h60
  text "SEMI-GLOSS" at 13312,3414.07 h60
  text "IMMERSION GOLD (ENIG)" at 12394.46,3241.94 h60
  text "ENEPIG" at 13732,3234.72 h60
  text "SURFACE FINISH:" at 11333.46,3233.72 h60
  text "X" at 12216.46,3233.72 h60
  text "IMM. TIN/SILVER OR EQUIV" at 11663,3096.4 h60
  text "OTHER" at 13094.46,3092.47 h60
  text "ARRAY/PANEL:" at 11333.46,2937.09 h60
  text "CUT AND TRIM PER M1 BOARD OUTLINE" at 12394.46,2928.87 h60
  text "N.C. ROUTE" at 12394.46,2792.9 h60
  text "X" at 13082.46,2792.9 h60
  text "V. SCORE" at 13260.46,2792.9 h60
  text "CERTIFICATION:" at 11333.46,2663.77 h60
  text "MATERIALS AND WORKMANSHIP FOR ALL PCBS" at 12058.46,2663.77 h60
  text "TO MEET OR EXCEED THE REQUIREMENTS OF:" at 12058.46,2569.71 h60
  text "X" at 11695.97,2441.08 h60
  text "ANSI IPC-A-600F CLASS ->" at 11823.96,2441.08 h60
  text "X" at 13471.97,2441.08 h60
  text "2" at 13581.96,2441.08 h60
  text "1" at 13266.96,2439.58 h60
  text "3" at 13935.96,2439.58 h60
  text "X" at 12507.97,2293.39 h60
  text "RoHS" at 12635.96,2293.39 h60
  text "OTHER" at 13280.36,2293.39 h60
  text "PER ORDER" at 13677.42,2293.39 h60
  text "ALL BOARDS MUST MEET OR EXCEED UL94-V0 REQUIREMENTS." at 11361,2139.57 h60
  text "PCB MUST BEAR THE UL94V-0 UL REGISTERED MATERIAL ID NUMBER" at 11361,2023.5 h60
  text "ADDITIONAL REQUIREMENTS:" at 11333.46,1854.08 h60
  text "MICROSECTION:" at 11408.23,1746.95 h60
  text "YES" at 12313.96,1746.95 h60
  text "REQUIRED" at 13175.46,1602.62 h60
  text "BARE BOARD ELEC. TEST:" at 11408.23,1599.76 h60
  text "NONE" at 12713.96,1599.76 h60
  text "X" at 13057.46,1599.76 h60
  text "PER ORDER" at 13767.46,1599.76 h60
  text "XX MIL VIAS REQUIRE NON-CONDUCTIVE FILL AND PLANARIZE" at 11576.38,1394.82 h59
  text "XX MIL VIAS REQUIRE CONDUCTIVE FILL AND PLANARIZE" at 11584.38,1290.84 h60
  text "OUTER XX MIL TRACES REQUIRE 50 OHM SINGLE-ENDED IMPEDANCE" at 11583.39,1127.46 h58
  text "LAYER 2 & 3 (INNER LAYERS) XX MIL WIDE, XX MIL SPACE / TRACES REQUIRE 100 OHM DIFFERENTIAL IMPEDANCE" at 11575.39,891.74 h60
  text ".Layer_Name" at 577,-858.49 h60
M11 Gerber Information:
  lines w10: -292,-930.17 6308,-930.17 ; -292,-726.83 6310,-726.83 ; -292,-523.5 -292,-1133.5 3713,-1133.5 6310,-1133.5 6310,-523.5 -291.5,-523.5 -291.5,-1133.5 1284,-1133.5 ; 2173,-1133.5 2173,-523.5 ; 3440,-726.83 3440,-523.5 ; 4280,-726.83 4280,-523.5 ; 4902,-1140 4902,-937.17
  text "ALL ARTWORK VIEWED FROM TOP SIDE" at -228.5,-655.67 h60
  text "BOARD #:" at 2248,-655.67 h60
  text ".PRJ_Number" at 2793.5,-655.67 h60
  text "REV:" at 3638,-655.67 h60
  text ".PCB_Rev" at 3929.5,-655.67 h60
  text "SVN REV:" at 4476,-655.67 h60
  text ".VersionControl_RevNumber" at 4982,-655.67 h60
  text "LAYER NAME =" at -228.5,-858.49 h60
  text "TID #:" at 2248,-859 h60
  text ".TID" at 2793.5,-859 h60
  text "PLOT NAME =" at -228.5,-1064.34 h60
  text ".plot_File_Name" at 577,-1064.34 h60
  text "GENERATED    :" at 2250,-1064.34 h60
  text ".Print_Date" at 3119.5,-1064.34 h60
  text ".Print_Time" at 3848.5,-1064.34 h60
  text "TEXAS INSTRUMENTS" at 5113,-1064.34 h60
M12 Stackup:
  drawing of 399 lines, arcs and shapes, not listed
  text "Layer" at 6667.2,7476.14 h60
  text "Name" at 7077.11,7476.14 h60
  text "Material" at 8016.85,7476.14 h60
  text "Thickness" at 8876.62,7476.14 h60
  text "Constant" at 9526.45,7476.14 h60
  text "Board Layer Stack" at 10096.31,7476.14 h60
  text "Top Overlay" at 7077.11,7356.14 h60
  text "Top Solder" at 7077.11,7236.14 h60
  text "Solder Resist" at 8016.85,7236.14 h60
  text "0.40mil" at 8876.62,7236.14 h60
  text "3.5" at 9526.45,7236.14 h60
  text "1" at 6667.2,7116.14 h60
  text "Top Layer" at 7077.11,7116.14 h60
  text "2.80mil" at 8876.62,7116.14 h60
  text "Dielectric 1" at 7077.11,6996.14 h60
  text "PP-006" at 8016.85,6996.14 h60
  text "7.00mil" at 8876.62,6996.14 h60
  text "4.1" at 9526.45,6996.14 h60
  text "2" at 6667.2,6876.14 h60
  text "Signal Layer 1" at 7077.11,6876.14 h60
  text "CF-004" at 8016.85,6876.14 h60
  text "2.80mil" at 8876.62,6876.14 h60
  text "Dielectric 2" at 7077.11,6756.14 h60
  text "7.00mil" at 8876.62,6756.14 h60
  text "4.2" at 9526.45,6756.14 h60
  text "3" at 6667.2,6636.14 h60
  text "Signal Layer 2" at 7077.11,6636.14 h60
  text "2.80mil" at 8876.62,6636.14 h60
  text "Dielectric3" at 7077.11,6516.14 h60
  text "FR-4" at 8016.85,6516.14 h60
  text "7.00mil" at 8876.62,6516.14 h60
  text "4.2" at 9526.45,6516.14 h60
  text "4" at 6667.2,6396.14 h60
  text "Signal Layer 3" at 7077.11,6396.14 h60
  text "2.80mil" at 8876.62,6396.14 h60
  text "Dielectric 4" at 7077.11,6276.14 h60
  text "7.00mil" at 8876.62,6276.14 h60
  text "4.2" at 9526.45,6276.14 h60
  text "5" at 6667.2,6156.14 h60
  text "Signal Layer 4" at 7077.11,6156.14 h60
  text "CF-004" at 8016.85,6156.14 h60
  text "2.80mil" at 8876.62,6156.14 h60
  text "Dielectric 5" at 7077.11,6036.14 h60
  text "PP-006" at 8016.85,6036.14 h60
  text "7.00mil" at 8876.62,6036.14 h60
  text "4.1" at 9526.45,6036.14 h60
  text "6" at 6667.2,5916.14 h60
  text "Bottom Layer" at 7077.11,5916.14 h60
  text "2.80mil" at 8876.62,5916.14 h60
  text "Bottom Solder" at 7077.11,5796.14 h60
  text "Solder Resist" at 8016.85,5796.14 h60
  text "0.40mil" at 8876.62,5796.14 h60
  text "3.5" at 9526.45,5796.14 h60
  text "Bottom Overlay" at 7077.11,5676.14 h60
  text ".Layer_Name" at 577,-858.49 h60
M13 Component Bodies Top:
  text ".Layer_Name" at 577,-858.49 h60
M14 Component Bodies Bottom:
  text ".Layer_Name" at 577,-858.49 h60
M15 Courtyards Top:
  text ".Layer_Name" at 577,-858.49 h60
M16 Courtyards Bottom:
  text ".Layer_Name" at 577,-858.49 h60
Drill Drawing:
  text ".Layer_Name" at 3789.5,536.51 h60
M17 Embedded Cavity:
  text ".Layer_Name" at 577,-858.49 h60
M18 Embedded Assembly:
  text ".Layer_Name" at 577,-858.49 h60
M19 Embedded Keepout:
  text ".Layer_Name" at 577,-858.49 h60

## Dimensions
3261.7,720 to 3262.5,2567.5 on M2 Board Dimensions
3261.7,720 to 6483.42,720 on M2 Board Dimensions
0,-400 to 1000,-400 on M2 Board Dimensions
